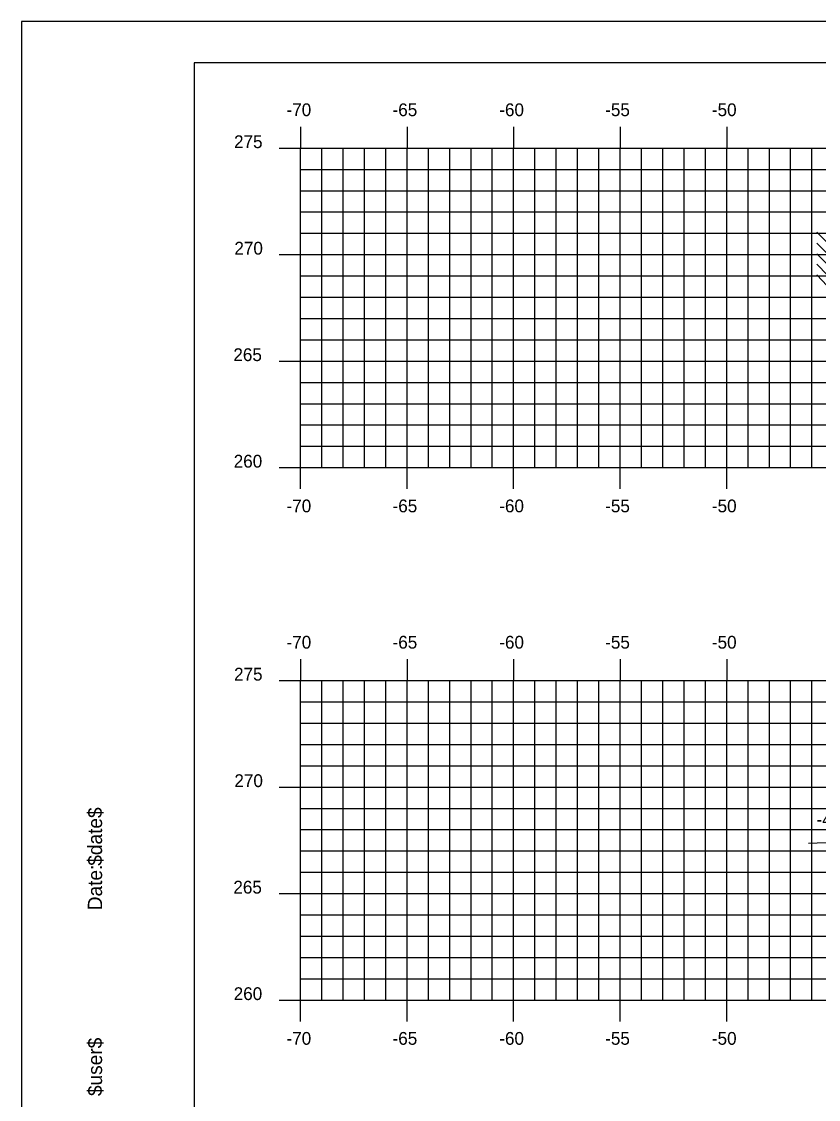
# Model space of a CAD drawing. Extents: x 855344 to 855514, y 366268 to 366378.
# Drawn here: x 855344 to 855381.4, y 366327.6 to 366378.2 of the extents above; entities that cross this region are included whole.
import ezdxf

# ---------------------------------------------------------------- set-up
doc = ezdxf.new("R2010")
doc.units = 0
for name, color, linetype in [('BORDER', 7, 'Continuous'), ('D_Text_Standard', 7, 'Continuous'), ('H_V ANNOTATION', 7, 'Continuous'), ('MAJOR', 7, 'Continuous'), ('MINOR', 7, 'Continuous'), ('PLOT BOUNDARY', 7, 'Continuous'), ('S_Buildings', 7, 'Continuous'), ('S_Roadway_Centerline', 7, 'Continuous')]:
    doc.layers.add(name, color=color, linetype=linetype)

msp = doc.modelspace()

# ---------------------------------------------------------------- linework, layer by layer
at = {"layer": 'BORDER'}
for p, q in [((855512.11, 366376.236), (855352.11, 366376.236)), ((855352.11, 366376.236), (855352.11, 366271.236))]:
    msp.add_line(p, q, dxfattribs=at)
at = {"layer": 'MAJOR'}
for p, q in [((855357.11, 366373.238), (855357.11, 366372.236)), ((855362.11, 366373.238), (855362.11, 366372.236)), ((855367.11, 366373.238), (855367.11, 366372.236)), ((855372.11, 366373.238), (855372.11, 366372.236)), ((855377.11, 366373.238), (855377.11, 366372.236)), ((855356.108, 366372.236), (855357.11, 366372.236)), ((855357.11, 366372.236), (855497.11, 366372.236)), ((855357.11, 366357.236), (855357.11, 366372.236)), ((855357.11, 366357.236), (855357.11, 366372.236)), ((855357.11, 366372.236), (855497.11, 366372.236)), ((855362.11, 366357.236), (855362.11, 366372.236)), ((855367.11, 366357.236), (855367.11, 366372.236)), ((855372.11, 366357.236), (855372.11, 366372.236)), ((855377.11, 366357.236), (855377.11, 366372.236)), ((855356.108, 366367.236), (855357.11, 366367.236)), ((855357.11, 366367.236), (855497.11, 366367.236)), ((855356.108, 366362.236), (855357.11, 366362.236)), ((855357.11, 366362.236), (855497.11, 366362.236)), ((855356.108, 366357.236), (855357.11, 366357.236)), ((855357.11, 366357.236), (855497.11, 366357.236)), ((855357.11, 366357.236), (855497.11, 366357.236)), ((855357.11, 366356.234), (855357.11, 366357.236)), ((855362.11, 366356.234), (855362.11, 366357.236)), ((855367.11, 366356.234), (855367.11, 366357.236)), ((855372.11, 366356.234), (855372.11, 366357.236)), ((855377.11, 366356.234), (855377.11, 366357.236)), ((855357.11, 366348.238), (855357.11, 366347.236)), ((855362.11, 366348.238), (855362.11, 366347.236)), ((855367.11, 366348.238), (855367.11, 366347.236)), ((855372.11, 366348.238), (855372.11, 366347.236)), ((855377.11, 366348.238), (855377.11, 366347.236)), ((855356.108, 366347.236), (855357.11, 366347.236)), ((855357.11, 366347.236), (855497.11, 366347.236)), ((855357.11, 366332.236), (855357.11, 366347.236)), ((855357.11, 366332.236), (855357.11, 366347.236)), ((855357.11, 366347.236), (855497.11, 366347.236)), ((855362.11, 366332.236), (855362.11, 366347.236)), ((855367.11, 366332.236), (855367.11, 366347.236)), ((855372.11, 366332.236), (855372.11, 366347.236)), ((855377.11, 366332.236), (855377.11, 366347.236)), ((855356.108, 366342.236), (855357.11, 366342.236)), ((855357.11, 366342.236), (855497.11, 366342.236)), ((855356.108, 366337.236), (855357.11, 366337.236)), ((855357.11, 366337.236), (855497.11, 366337.236)), ((855356.108, 366332.236), (855357.11, 366332.236)), ((855357.11, 366332.236), (855497.11, 366332.236)), ((855357.11, 366332.236), (855497.11, 366332.236)), ((855357.11, 366331.234), (855357.11, 366332.236)), ((855362.11, 366331.234), (855362.11, 366332.236)), ((855367.11, 366331.234), (855367.11, 366332.236)), ((855372.11, 366331.234), (855372.11, 366332.236)), ((855377.11, 366331.234), (855377.11, 366332.236))]:
    msp.add_line(p, q, dxfattribs=at)
at = {"layer": 'MINOR'}
for p, q in [((855358.11, 366357.236), (855358.11, 366372.236)), ((855359.11, 366357.236), (855359.11, 366372.236)), ((855360.11, 366357.236), (855360.11, 366372.236)), ((855361.11, 366357.236), (855361.11, 366372.236)), ((855363.11, 366357.236), (855363.11, 366372.236)), ((855364.11, 366357.236), (855364.11, 366372.236)), ((855365.11, 366357.236), (855365.11, 366372.236)), ((855366.11, 366357.236), (855366.11, 366372.236)), ((855368.11, 366357.236), (855368.11, 366372.236)), ((855369.11, 366357.236), (855369.11, 366372.236)), ((855370.11, 366357.236), (855370.11, 366372.236)), ((855371.11, 366357.236), (855371.11, 366372.236)), ((855373.11, 366357.236), (855373.11, 366372.236)), ((855374.11, 366357.236), (855374.11, 366372.236)), ((855375.11, 366357.236), (855375.11, 366372.236)), ((855376.11, 366357.236), (855376.11, 366372.236)), ((855378.11, 366357.236), (855378.11, 366372.236)), ((855379.11, 366357.236), (855379.11, 366372.236)), ((855380.11, 366357.236), (855380.11, 366372.236)), ((855381.11, 366357.236), (855381.11, 366372.236)), ((855357.11, 366371.236), (855497.11, 366371.236)), ((855357.11, 366371.236), (855358.112, 366371.236)), ((855357.11, 366370.236), (855497.11, 366370.236)), ((855357.11, 366370.236), (855358.112, 366370.236)), ((855357.11, 366369.236), (855497.11, 366369.236)), ((855357.11, 366369.236), (855358.112, 366369.236)), ((855357.11, 366368.236), (855497.11, 366368.236)), ((855357.11, 366368.236), (855358.112, 366368.236)), ((855357.11, 366366.236), (855497.11, 366366.236)), ((855357.11, 366366.236), (855358.112, 366366.236)), ((855357.11, 366365.236), (855497.11, 366365.236)), ((855357.11, 366365.236), (855358.112, 366365.236)), ((855357.11, 366364.236), (855497.11, 366364.236)), ((855357.11, 366364.236), (855358.112, 366364.236)), ((855357.11, 366363.236), (855497.11, 366363.236)), ((855357.11, 366363.236), (855358.112, 366363.236)), ((855357.11, 366361.236), (855497.11, 366361.236)), ((855357.11, 366361.236), (855358.112, 366361.236)), ((855357.11, 366360.236), (855497.11, 366360.236)), ((855357.11, 366360.236), (855358.112, 366360.236)), ((855357.11, 366359.236), (855497.11, 366359.236)), ((855357.11, 366359.236), (855358.112, 366359.236)), ((855357.11, 366358.236), (855497.11, 366358.236)), ((855357.11, 366358.236), (855358.112, 366358.236)), ((855357.11, 366332.236), (855357.11, 366347.236)), ((855358.11, 366332.236), (855358.11, 366347.236)), ((855359.11, 366332.236), (855359.11, 366347.236)), ((855360.11, 366332.236), (855360.11, 366347.236)), ((855361.11, 366332.236), (855361.11, 366347.236)), ((855363.11, 366332.236), (855363.11, 366347.236)), ((855364.11, 366332.236), (855364.11, 366347.236)), ((855365.11, 366332.236), (855365.11, 366347.236)), ((855366.11, 366332.236), (855366.11, 366347.236)), ((855368.11, 366332.236), (855368.11, 366347.236)), ((855369.11, 366332.236), (855369.11, 366347.236)), ((855370.11, 366332.236), (855370.11, 366347.236)), ((855371.11, 366332.236), (855371.11, 366347.236)), ((855373.11, 366332.236), (855373.11, 366347.236)), ((855374.11, 366332.236), (855374.11, 366347.236)), ((855375.11, 366332.236), (855375.11, 366347.236)), ((855376.11, 366332.236), (855376.11, 366347.236)), ((855378.11, 366332.236), (855378.11, 366347.236)), ((855379.11, 366332.236), (855379.11, 366347.236)), ((855380.11, 366332.236), (855380.11, 366347.236)), ((855381.11, 366332.236), (855381.11, 366347.236)), ((855357.11, 366346.236), (855497.11, 366346.236)), ((855357.11, 366346.236), (855358.112, 366346.236)), ((855357.11, 366345.236), (855497.11, 366345.236)), ((855357.11, 366345.236), (855358.112, 366345.236)), ((855357.11, 366344.236), (855497.11, 366344.236)), ((855357.11, 366344.236), (855358.112, 366344.236)), ((855357.11, 366343.236), (855497.11, 366343.236)), ((855357.11, 366343.236), (855358.112, 366343.236)), ((855357.11, 366341.236), (855497.11, 366341.236)), ((855357.11, 366341.236), (855358.112, 366341.236)), ((855357.11, 366340.236), (855497.11, 366340.236)), ((855357.11, 366340.236), (855358.112, 366340.236)), ((855357.11, 366339.236), (855497.11, 366339.236)), ((855357.11, 366339.236), (855358.112, 366339.236)), ((855357.11, 366338.236), (855497.11, 366338.236)), ((855357.11, 366338.236), (855358.112, 366338.236)), ((855357.11, 366336.236), (855497.11, 366336.236)), ((855357.11, 366336.236), (855358.112, 366336.236)), ((855357.11, 366335.236), (855497.11, 366335.236)), ((855357.11, 366335.236), (855358.112, 366335.236)), ((855357.11, 366334.236), (855497.11, 366334.236)), ((855357.11, 366334.236), (855358.112, 366334.236)), ((855357.11, 366333.236), (855497.11, 366333.236)), ((855357.11, 366333.236), (855358.112, 366333.236))]:
    msp.add_line(p, q, dxfattribs=at)
at = {"layer": 'PLOT BOUNDARY'}
msp.add_lwpolyline([(855344.016, 366268.177), (855514.016, 366268.177), (855514.016, 366378.177), (855344.016, 366378.177)], close=True, dxfattribs=at)
at = {"layer": 'S_Buildings'}
for p, q in [((855382.843, 366366.782), (855381.333, 366368.291)), ((855382.843, 366366.289), (855381.333, 366367.766)), ((855382.843, 366365.764), (855381.333, 366367.274)), ((855382.318, 366365.764), (855381.333, 366366.782)), ((855381.826, 366365.764), (855381.333, 366366.289))]:
    msp.add_line(p, q, dxfattribs=at)
at = {"layer": 'S_Roadway_Centerline'}
msp.add_lwpolyline([(855384.275, 366339.699), (855382.187, 366339.633), (855380.943, 366339.594)], dxfattribs=at)

# ---------------------------------------------------------------- texts
at = {"layer": 'BORDER'}
for s, p in [('$date$', (855347.795, 366338.542)), ('Date:', (855347.795, 366336.453)), ('$user$', (855347.795, 366327.728))]:
    msp.add_text(s, height=0.6696, rotation=90, dxfattribs=at).set_placement(p)
at = {"layer": 'D_Text_Standard'}
msp.add_text("-44.9'", height=0.6, dxfattribs=at).set_placement((855381.326, 366340.42))
at = {"layer": 'H_V ANNOTATION'}
for s, p in [('-70', (855356.451, 366373.736)), ('-65', (855361.427, 366373.736)), ('-60', (855366.435, 366373.736)), ('-55', (855371.406, 366373.736)), ('-50', (855376.414, 366373.736)), ('275', (855353.988, 366372.236)), ('270', (855354.004, 366367.236)), ('265', (855353.956, 366362.236)), ('260', (855353.972, 366357.236)), ('-70', (855356.451, 366355.136)), ('-65', (855361.427, 366355.136)), ('-60', (855366.435, 366355.136)), ('-55', (855371.406, 366355.136)), ('-50', (855376.414, 366355.136)), ('-70', (855356.451, 366348.736)), ('-65', (855361.427, 366348.736)), ('-60', (855366.435, 366348.736)), ('-55', (855371.406, 366348.736)), ('-50', (855376.414, 366348.736)), ('275', (855353.988, 366347.236)), ('270', (855354.004, 366342.236)), ('265', (855353.956, 366337.236)), ('260', (855353.972, 366332.236)), ('-70', (855356.451, 366330.136)), ('-65', (855361.427, 366330.136)), ('-60', (855366.435, 366330.136)), ('-55', (855371.406, 366330.136)), ('-50', (855376.414, 366330.136))]:
    msp.add_text(s, height=0.6, dxfattribs=at).set_placement(p)

doc.saveas('drawing.dxf')
